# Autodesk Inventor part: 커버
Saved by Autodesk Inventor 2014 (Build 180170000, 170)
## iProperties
Created: 2026-09
Part Number: 커버
Material: 알루미늄 6061
Document SubType Name: Modeling
Designer: dg
Density: 2.71 g/cm^3
Appearance: 알루미늄 - 평지
Mass: 418.915 g
Surface Area: 249.609 cm^2
Volume: 154.581 cm^3
Author: jhkim
Creation Date: 2026-08-26
Sending System: Autodesk Inventor 2027
Preprocessor: ST-DEVELOPER v20.1
Author: dg
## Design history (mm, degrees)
node "커버1"
node "솔리드2"
node "기준1"
